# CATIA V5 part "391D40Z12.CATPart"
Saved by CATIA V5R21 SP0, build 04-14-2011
Part number: 391D40Z12
Bounding box of the stored display mesh (mm): x -48.732 to 48.732, y -12 to 12, z -48.732 to 48.732
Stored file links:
  C:\Users\ALI OZGUN\Desktop\alhan\TESLIMEDILEN3\391D40Z12.CATPart
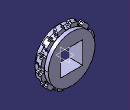
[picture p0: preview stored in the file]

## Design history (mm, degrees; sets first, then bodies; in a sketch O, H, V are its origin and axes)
Body1 (main body)
  Sketch1 on zx-plane, origin (0, 0, 0), H (-1, 0, 0), V (0, 0, 1)
    circle A1 centre (0, 0) radius 42.25
    radius A1 = 42.25
  Pad1: profile Sketch1, direction (0, 1, 0), length 14
  Sketch2 on zx-plane, origin (0, 0, 0), H (-1, 0, 0), V (0, 0, 1)
    circle A1 centre (0, 0) radius 49
    radius A1 = 49
  Pad2: profile Sketch2, direction (0, 1, 0), length 5
  Sketch3 on end face of Pad2, origin (0, 5, 0), H (-1, 0, 0), V (0, 0, 1)
    point P1 (-6.5, 48.567)
    line L1 (-6.5, 48.567) -> (-4.25, 42.7895)
    point P2 (-4.25, 42.7895)
    arc A1 centre (0, 0) radius 43 from (4.25, 42.7895) to (-4.25, 42.7895) ccw
    reference projected circle E1 centre (0, 0) radius 49 from edge [face of Pad2 from Sketch2.A1 | end face of Pad2]
    point P3 (4.25, 42.7895)
    point P4 (6.5, 48.567)
    line L2 (6.5, 48.567) -> (4.25, 42.7895)
    radius A1 = 43
    distance P1 V = 6.5
    distance P2 V = 4.25
    coincidence: P1 E1
    symmetry: P2 P3 V, P1 P4 V, L1 L2 V
  Pocket1: profile Sketch3, direction (0, -1, 0), length 5
  CircPattern1: of Pocket1, instances 12, angular step 30, axis from face of Pad1 from Sketch1.A1
  Fillet1: radius 2, on edge [face of CircPattern1 | face of Pad2 from Sketch2.A1] (x11); edge [face of Pad2 from Sketch2.A1 | face of CircPattern1] (x11); edge [face of Pocket1 from Sketch3.L1 | face of Pad2 from Sketch2.A1]; edge [face of Pad2 from Sketch2.A1 | face of Pocket1 from Sketch3.L2]; edge [face of CircPattern1 | face of CircPattern1] (x22); edge [face of Pocket1 from Sketch3.L2 | face of Pocket1 from Sketch3.A1]; edge [face of Pocket1 from Sketch3.A1 | face of Pocket1 from Sketch3.L1]
Body2
  Solid1: linked copy from another document
  Body3
    Solid2: linked copy from another document
    Symmetry1: Reference face of Solid2, ToTransfor Solid2
    Rotate1: Axis Sketch4, Angle 3.5, ToTransfor Symmetry1
    Sketch4 on yz-plane, origin (0, 0, 0), H (0, 1, 0), V (0, 0, 1)
      line L1 (68.9983, 0) -> (-60.7772, 0)
      point P1 (68.9983, 0)
      coincidence: P1 H
      horizontal: L1 H
  Add1: tool Body3
  Sketch5 on face of Solid1, origin (0, 14, 0), H (-1, 0, 0), V (0, 0, 1)
    line L1 (20, 20) -> (20, -20)
    line L2 (20, -20) -> (-20, -20)
    line L3 (-20, -20) -> (-20, 20)
    line L4 (-20, 20) -> (20, 20)
    length L4 = 40
    length L1 = 40
    vertical: L1 V, L3 V
    horizontal: L2 H, L4 H
    equidistance: L1 L3 O, L2 L4 O
  Pocket2: profile Sketch5, direction (0, -1, 0), through (limit type 6)
  Sketch6 on face of Solid1, origin (0, 14, 0), H (-1, 0, 0), V (0, 0, 1)
    construction line L1 (-18.4923, 18.4923) -> (16.4725, -16.4725)
    axis line L2 (23.8397, 23.8397) -> (-21.8636, -21.8636)
    construction circle A1 centre (0, 0) radius 21
    arc A2 centre (-15.1493, -15.1493) radius 30 from (-14.8492, 14.8492) to (0, 10.7448) cw
    point P6 (-14.8492, 14.8492)
    point P7 (14.8492, -14.8492)
    point P8 (6.0639, 6.0639)
    point P9 (14.8492, -14.8492)
    point P10 (-14.8492, 14.8492)
    arc A3 centre (15.1493, 15.1493) radius 30 from (-14.8492, 14.8492) to (-10.7448, 0) ccw
    point P12 (-14.8492, -14.8492)
    point P13 (14.8492, 14.8492)
    arc A4 centre (-15.1493, 15.1493) radius 30 from (14.8492, 14.8492) to (10.7448, 0) cw
    point P15 (-14.8492, -14.8492)
    point P16 (14.8492, 14.8492)
    arc A5 centre (15.1493, -15.1493) radius 30 from (14.8492, 14.8492) to (0, 10.7448) ccw
    arc A6 centre (15.1493, -15.1493) radius 30 from (-10.7448, 0) to (-14.8492, -14.8492) ccw
    arc A7 centre (15.1493, 15.1493) radius 30 from (0, -10.7448) to (14.8492, -14.8492) ccw
    arc A8 centre (-15.1493, 15.1493) radius 30 from (0, -10.7448) to (-14.8492, -14.8492) cw
    point P20 (10.7448, 0)
    arc A9 centre (-15.1493, -15.1493) radius 30 from (10.7448, 0) to (14.8492, -14.8492) cw
    angle L1 V = 45
    angle V L2 = 45
    radius A1 = 21
    radius A2 = 30
    coincidence: L1 O, L2 O, P6 A1, P6 L1, P7 A1, P7 L1, A2 P8, P8 L2, A5 A6, A3 A7, A4 A8, A2 P20, A2 A9, P6 P10, P7 P9, P12 P15, P13 P16
    symmetry: P7 P9 L1, P6 P10 L1, A2 A3 L1, P9 P12 V, P10 P13 V, A3 A4 V, P7 P15 V, P6 P16 V, A2 A5 V
  Thickness1: Face (face of Solid1; face of Solid2), Thickness -2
